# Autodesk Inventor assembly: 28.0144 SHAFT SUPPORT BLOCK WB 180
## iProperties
Created: 2007-06
Part Number: 28.0144 SHAFT SUPPORT BLOCK WB 180
Document SubType Name: Assembly
Designer: Andy Moles
Author: Andy Moles
